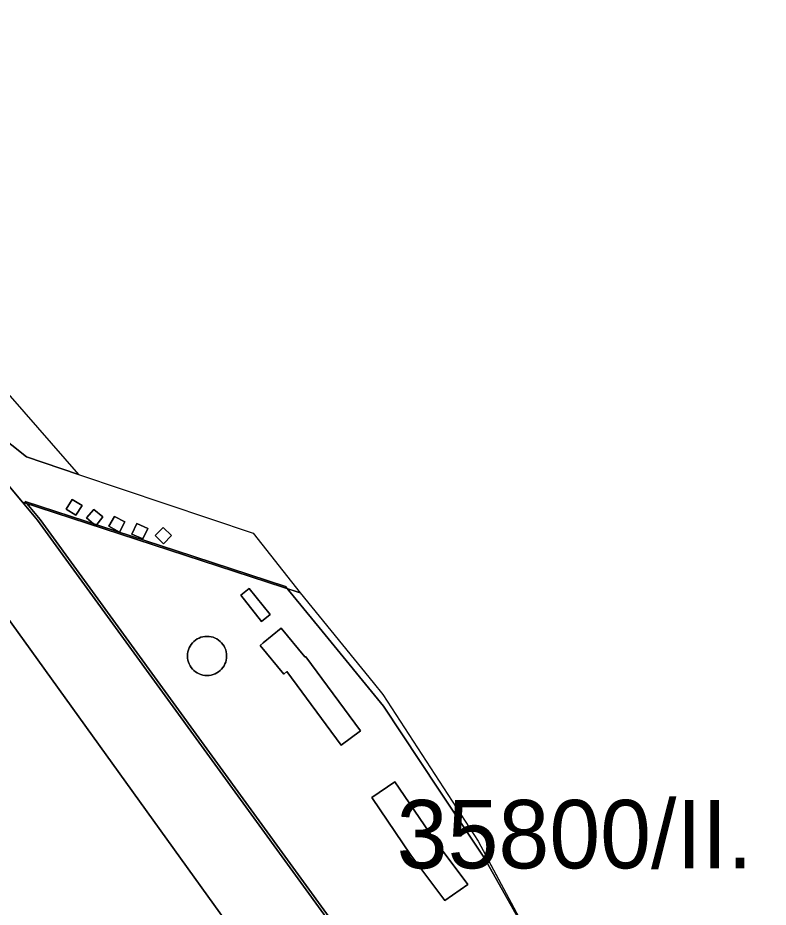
# Model space of a CAD drawing. Extents: x -535894 to -532827, y -1165802 to -1163635.
# Drawn here: x -533178.9 to -533014.4, y -1164702.6 to -1164507.5 of the extents above; entities that cross this region are included whole.
import ezdxf

# ---------------------------------------------------------------- set-up
doc = ezdxf.new("R2010")
doc.units = 0
for name, color, linetype in [('BPEJ_s', 7, 'Continuous'), ('ostatni_s', 7, 'Continuous'), ('PUPFL_s', 7, 'Continuous'), ('voda_s', 7, 'Continuous')]:
    doc.layers.add(name, color=color, linetype=linetype)

msp = doc.modelspace()

# ---------------------------------------------------------------- linework, layer by layer
at = {"layer": 'BPEJ_s'}
msp.add_lwpolyline([(-533217.69, -1164548.05), (-533165.64, -1164607.65), (-533127.31, -1164620.51), (-533116.98, -1164633.6), (-533101.02, -1164653.29), (-533098.87, -1164655.96), (-533077.99, -1164688.07), (-533064.041, -1164714.206), (-533076.582, -1164691.833), (-533086.643, -1164676.675), (-533098.703, -1164658.507), (-533112.188, -1164642.002), (-533120.195, -1164632.203), (-533144.122, -1164624.407), (-533177.323, -1164613.591), (-533174.02, -1164617.541), (-533099.729, -1164719.761)], dxfattribs=at)
msp.add_lwpolyline([(-533064.041, -1164714.206), (-533051.48, -1164737.74), (-533049.69, -1164741.02), (-533048.53, -1164743.15), (-533047.398, -1164743.989), (-533028.041, -1164779.71), (-533014.38, -1164808.947), (-533037.332, -1164819.2), (-533075.566, -1164758.607), (-533078.437, -1164753.841), (-533082.42, -1164747.231), (-533086.574, -1164740.34), (-533089.802, -1164734.991), (-533093.522, -1164728.812), (-533097.748, -1164722.487), (-533099.729, -1164719.761), (-533174.02, -1164617.541), (-533177.323, -1164613.591), (-533144.122, -1164624.407), (-533120.195, -1164632.203), (-533112.188, -1164642.002), (-533098.703, -1164658.507), (-533086.643, -1164676.675), (-533076.582, -1164691.833)], close=True, dxfattribs=at)
at = {"layer": 'ostatni_s'}
for points in [[(-533286.31, -1164461.99), (-533266.97, -1164486.26), (-533227.22, -1164536.15), (-533217.69, -1164548.05), (-533212.4, -1164563.33), (-533202.85, -1164583.35), (-533177.04, -1164603.82), (-533165.64, -1164607.65), (-533127.31, -1164620.51), (-533116.98, -1164633.6), (-533177.92, -1164613.75), (-533205.86, -1164580.27), (-533235.68, -1164545.17), (-533280.62, -1164497.03), (-533292.65, -1164484.53)], [(-533116.98, -1164633.6), (-533101.02, -1164653.29), (-533098.87, -1164655.96), (-533077.99, -1164688.07), (-533051.48, -1164737.74), (-533049.69, -1164741.02), (-533051.79, -1164739.92), (-533060.24, -1164735.48), (-533067.33, -1164731.75), (-533074.43, -1164728.01), (-533080.87, -1164725.97), (-533088.71, -1164723.46), (-533096.72, -1164721.02), (-533100.33, -1164719.92), (-533174.61, -1164617.7), (-533177.92, -1164613.75)], [(-533166.97, -1164613.12), (-533168.3, -1164615.25), (-533166.17, -1164616.6), (-533164.82, -1164614.46)], [(-533166.97, -1164613.12), (-533164.82, -1164614.46), (-533166.17, -1164616.6), (-533168.3, -1164615.25)], [(-533162.26, -1164615.36), (-533163.84, -1164617.2), (-533161.84, -1164618.92), (-533160.26, -1164616.97)], [(-533162.26, -1164615.36), (-533160.26, -1164616.97), (-533161.84, -1164618.92), (-533163.84, -1164617.2)], [(-533157.74, -1164616.87), (-533158.93, -1164619), (-533156.63, -1164620.28), (-533155.47, -1164618.03)], [(-533157.74, -1164616.87), (-533155.47, -1164618.03), (-533156.63, -1164620.28), (-533158.93, -1164619)], [(-533152.85, -1164618.41), (-533153.89, -1164620.73), (-533151.48, -1164621.81), (-533150.43, -1164619.54)], [(-533152.85, -1164618.41), (-533150.43, -1164619.54), (-533151.48, -1164621.81), (-533153.89, -1164620.73)], [(-533147.06, -1164619.31), (-533148.81, -1164621.03), (-533146.98, -1164622.9), (-533145.23, -1164621.07)], [(-533147.06, -1164619.31), (-533145.23, -1164621.07), (-533146.98, -1164622.9), (-533148.81, -1164621.03)], [(-533128.16, -1164632.66), (-533123.6, -1164638.37), (-533125.49, -1164639.89), (-533130.05, -1164634.17)], [(-533123.6, -1164638.37), (-533128.16, -1164632.66), (-533130.05, -1164634.17), (-533125.49, -1164639.89)], [(-533121.17, -1164641.34), (-533115.99, -1164647.64), (-533115.76, -1164647.68), (-533103.81, -1164663.92), (-533108.03, -1164667.03), (-533119.95, -1164650.91), (-533120.62, -1164651.45), (-533125.8, -1164645.15), (-533125.15, -1164644.61)], [(-533115.76, -1164647.68), (-533115.99, -1164647.64), (-533121.17, -1164641.34), (-533125.15, -1164644.61), (-533125.8, -1164645.15), (-533120.62, -1164651.45), (-533119.95, -1164650.91), (-533108.03, -1164667.03), (-533103.81, -1164663.92)], [(-533136.981, -1164651.746), (-533137.43, -1164651.77), (-533137.88, -1164651.746), (-533138.324, -1164651.676), (-533138.759, -1164651.56), (-533139.179, -1164651.398), (-533139.58, -1164651.194), (-533139.957, -1164650.949), (-533140.307, -1164650.666), (-533140.626, -1164650.347), (-533140.909, -1164649.997), (-533141.154, -1164649.62), (-533141.358, -1164649.219), (-533141.519, -1164648.799), (-533141.636, -1164648.364), (-533141.706, -1164647.92), (-533141.73, -1164647.47), (-533141.706, -1164647.021), (-533141.636, -1164646.576), (-533141.519, -1164646.141), (-533141.358, -1164645.721), (-533141.154, -1164645.32), (-533140.909, -1164644.942), (-533140.626, -1164644.593), (-533140.307, -1164644.275), (-533139.957, -1164643.991), (-533139.58, -1164643.746), (-533139.179, -1164643.542), (-533138.759, -1164643.381), (-533138.324, -1164643.264), (-533137.88, -1164643.194), (-533137.43, -1164643.17), (-533136.981, -1164643.194), (-533136.536, -1164643.264), (-533136.101, -1164643.381), (-533135.681, -1164643.542), (-533135.28, -1164643.746), (-533134.903, -1164643.991), (-533134.553, -1164644.275), (-533134.234, -1164644.593), (-533133.951, -1164644.942), (-533133.706, -1164645.32), (-533133.502, -1164645.721), (-533133.341, -1164646.141), (-533133.224, -1164646.576), (-533133.154, -1164647.021), (-533133.13, -1164647.47), (-533133.154, -1164647.92), (-533133.224, -1164648.364), (-533133.341, -1164648.799), (-533133.502, -1164649.219), (-533133.706, -1164649.62), (-533133.951, -1164649.997), (-533134.234, -1164650.347), (-533134.553, -1164650.666), (-533134.903, -1164650.949), (-533135.28, -1164651.194), (-533135.681, -1164651.398), (-533136.101, -1164651.56), (-533136.536, -1164651.676)], [(-533136.981, -1164651.746), (-533136.536, -1164651.676), (-533136.101, -1164651.56), (-533135.681, -1164651.398), (-533135.28, -1164651.194), (-533134.903, -1164650.949), (-533134.553, -1164650.666), (-533134.234, -1164650.347), (-533133.951, -1164649.997), (-533133.706, -1164649.62), (-533133.502, -1164649.219), (-533133.341, -1164648.799), (-533133.224, -1164648.364), (-533133.154, -1164647.92), (-533133.13, -1164647.47), (-533133.154, -1164647.021), (-533133.224, -1164646.576), (-533133.341, -1164646.141), (-533133.502, -1164645.721), (-533133.706, -1164645.32), (-533133.951, -1164644.942), (-533134.234, -1164644.593), (-533134.553, -1164644.275), (-533134.903, -1164643.991), (-533135.28, -1164643.746), (-533135.681, -1164643.542), (-533136.101, -1164643.381), (-533136.536, -1164643.264), (-533136.981, -1164643.194), (-533137.43, -1164643.17), (-533137.88, -1164643.194), (-533138.324, -1164643.264), (-533138.759, -1164643.381), (-533139.179, -1164643.542), (-533139.58, -1164643.746), (-533139.957, -1164643.991), (-533140.307, -1164644.275), (-533140.626, -1164644.593), (-533140.909, -1164644.942), (-533141.154, -1164645.32), (-533141.358, -1164645.721), (-533141.519, -1164646.141), (-533141.636, -1164646.576), (-533141.706, -1164647.021), (-533141.73, -1164647.47), (-533141.706, -1164647.92), (-533141.636, -1164648.364), (-533141.519, -1164648.799), (-533141.358, -1164649.219), (-533141.154, -1164649.62), (-533140.909, -1164649.997), (-533140.626, -1164650.347), (-533140.307, -1164650.666), (-533139.957, -1164650.949), (-533139.58, -1164651.194), (-533139.179, -1164651.398), (-533138.759, -1164651.56), (-533138.324, -1164651.676), (-533137.88, -1164651.746), (-533137.43, -1164651.77)], [(-533096.25, -1164675.12), (-533087.66, -1164687.7), (-533080.27, -1164697.63), (-533085.28, -1164701.13), (-533092.73, -1164691.17), (-533101.27, -1164678.5)], [(-533080.27, -1164697.63), (-533087.66, -1164687.7), (-533096.25, -1164675.12), (-533101.27, -1164678.5), (-533092.73, -1164691.17), (-533085.28, -1164701.13)]]:
    msp.add_lwpolyline(points, close=True, dxfattribs=at)
for points in [[(-533205.86, -1164580.27), (-533177.92, -1164613.75), (-533174.61, -1164617.7), (-533100.33, -1164719.92)], [(-533107.67, -1164741.3), (-533187.88, -1164629.82)]]:
    msp.add_lwpolyline(points, dxfattribs=at)
at = {"layer": 'PUPFL_s'}
msp.add_lwpolyline([(-533217.69, -1164548.05), (-533165.64, -1164607.65), (-533177.04, -1164603.82), (-533202.85, -1164583.35), (-533212.4, -1164563.33)], close=True, dxfattribs=at)
at = {"layer": 'voda_s'}
msp.add_lwpolyline([(-533187.88, -1164629.82), (-533107.67, -1164741.3), (-533065.72, -1164811.1), (-533067.05, -1164814.68), (-533067.75, -1164818), (-533068.04, -1164821.56), (-533067.67, -1164826.38), (-533066.32, -1164830), (-533081.23, -1164836.98), (-533082.55, -1164836.49), (-533086.18, -1164838.19), (-533086.66, -1164839.51), (-533100.24, -1164845.86), (-533101.59, -1164845.38), (-533105.21, -1164847.08), (-533105.69, -1164848.41), (-533120.66, -1164855.41), (-533122.43, -1164852.64), (-533125.12, -1164849.67), (-533128.35, -1164847.2), (-533129.85, -1164846.49), (-533148.43, -1164813.4), (-533174.44, -1164769.08), (-533216.56, -1164705.51)], dxfattribs=at)

# ---------------------------------------------------------------- texts
at = {"layer": 'BPEJ_s'}
msp.add_text('35800/II.', height=15, dxfattribs=at).set_placement((-533095.851, -1164694.064))

doc.saveas('drawing.dxf')
